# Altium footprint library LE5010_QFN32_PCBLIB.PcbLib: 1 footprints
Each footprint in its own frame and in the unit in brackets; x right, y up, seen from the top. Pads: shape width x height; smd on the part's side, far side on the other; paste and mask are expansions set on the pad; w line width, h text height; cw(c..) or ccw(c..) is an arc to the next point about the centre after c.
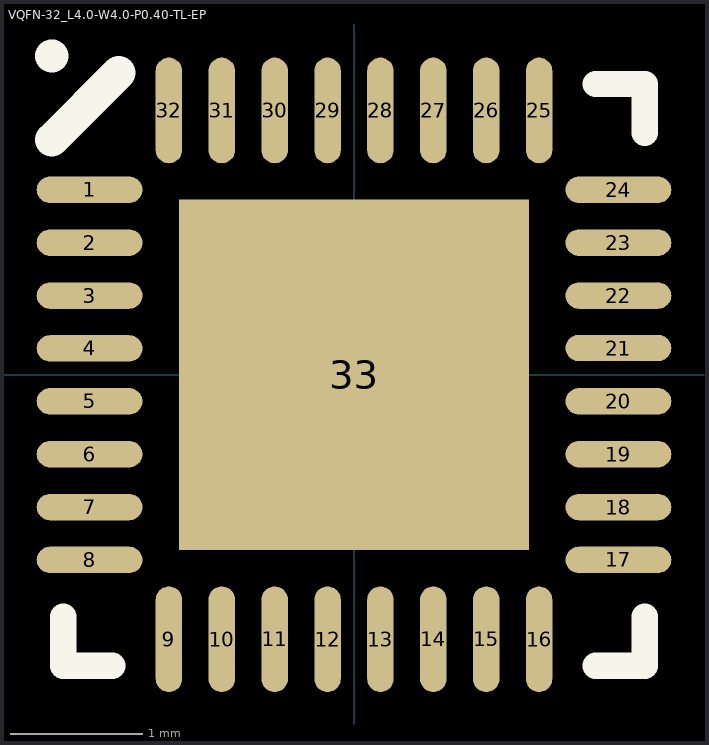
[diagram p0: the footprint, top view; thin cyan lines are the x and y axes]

## VQFN-32_L4.0-W4.0-P0.40-TL-EP [mm]
pads (33):
  oval 0.8x0.2 smd: 1(-2,1.4) 2(-2,1) 3(-2,0.6) 4(-2,0.2) 5(-2,-0.2) 6(-2,-0.6) 7(-2,-1) 8(-2,-1.4) 17(2,-1.4) 18(2,-1) 19(2,-0.6) 20(2,-0.2) 21(2,0.203) 22(2,0.6) 23(2,1) 24(2,1.4)
  oval 0.2x0.8 smd: 9(-1.4,-2) 10(-1,-2) 11(-0.6,-2) 12(-0.2,-2) 13(0.2,-2) 14(0.6,-2) 15(1,-2) 16(1.4,-2) 25(1.4,2) 26(1,2) 27(0.6,2) 28(0.2,2) 29(-0.2,2) 30(-0.6,2) 31(-1,2) 32(-1.4,2)
  rect 2.65x2.65 smd: 33(0,0)
Top Overlay:
  circle w0.25: c-2.286,2.413 r0
  lines w0.2: -2.2,-1.83 -2.2,-2.2 -1.83,-2.2 ; 1.83,-2.2 2.2,-2.2 2.2,-1.83 ; 1.83,2.2 2.2,2.2 2.2,1.83
  lines w0.254: -2.286,1.778 -1.778,2.286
